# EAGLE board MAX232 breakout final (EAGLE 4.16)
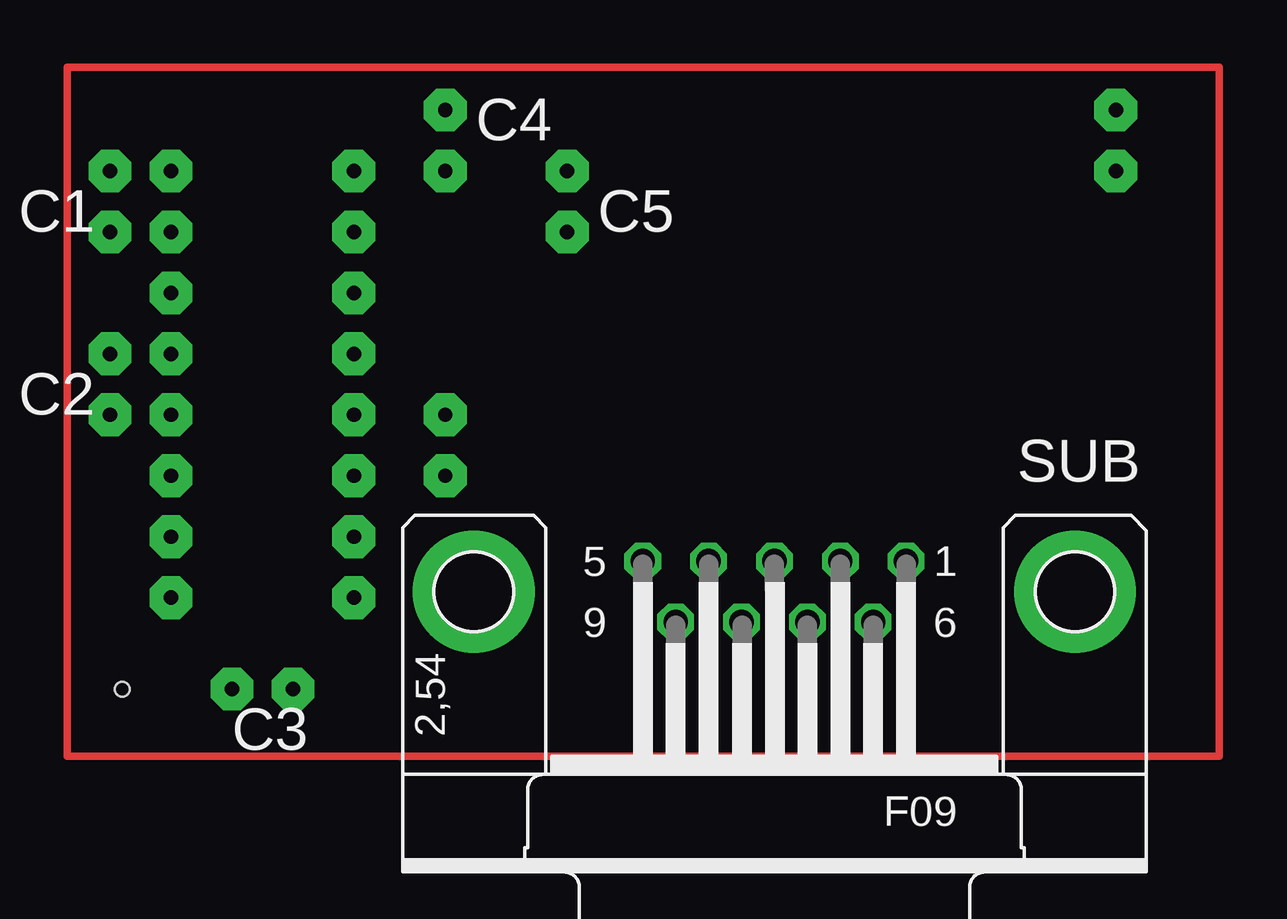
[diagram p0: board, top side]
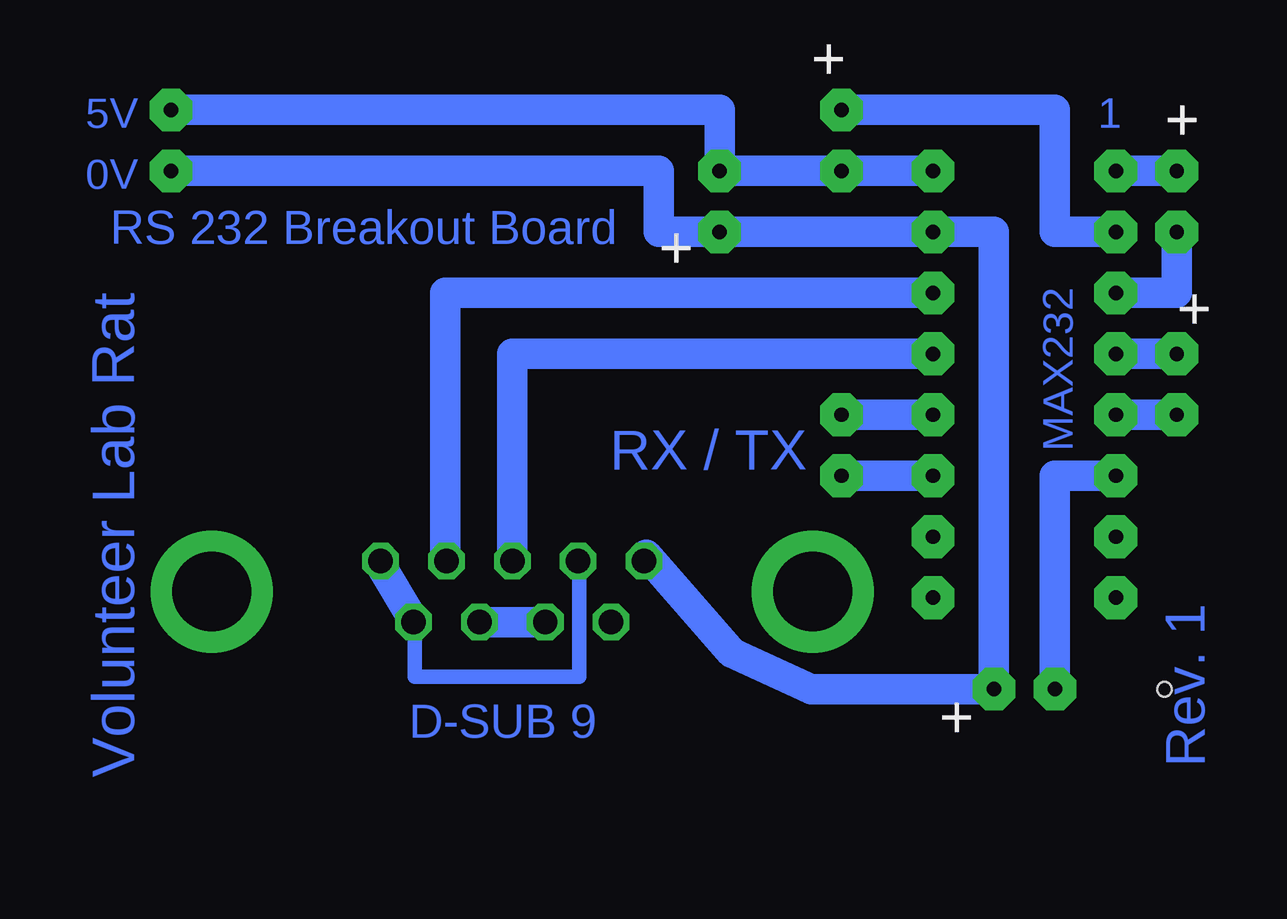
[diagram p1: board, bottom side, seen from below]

No outline drawn. Coordinates in mm, seen from the top.
Copper layers (1*16): Top 0.035mm / dielectric 1.5mm / Bottom 0.035mm
Design rules "default": minimum track width 10mil, minimum drill 24mil, track to track 8mil, track to pad 8mil, pad to pad 8mil, via to via 8mil, smd to smd 8mil, copper to edge 40mil, drill to drill 8mil, minimum pad ring 10mil, minimum via ring 8mil, stop-mask expansion 4mil, vias tented up to drill 0mil, thermal gap 10mil
Holes 0.6 mm at 25.91,22.86

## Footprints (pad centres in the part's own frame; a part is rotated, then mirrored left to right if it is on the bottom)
F09HP = drill 1.016 octagon: 1 -5.486,-1.27; 2 -2.743,-1.27; 3 0,-1.27; 4 2.743,-1.27; 5 5.486,-1.27; 6 -4.115,1.27; 7 -1.372,1.27; 8 1.372,1.27; 9 4.115,1.27 | drill 3.302 pad 5.08 round: G1 -12.522,0; G2 12.522,0

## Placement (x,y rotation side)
SUB  [F09HP]  53.09,26.92 180 top

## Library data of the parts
SUB = con-subd

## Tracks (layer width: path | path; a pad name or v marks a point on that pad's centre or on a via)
S$1  (via drill 0.6 pad 1.78)
  other vias: 27.94,26.67
S$2  (via drill 0.6 pad 1.78)
  other vias: 27.94,29.21
S$4  (via drill 0.6 pad 1.78)
  Bottom 1.27: v25.4,34.29 v27.94,34.29
S$5  (via drill 0.6 pad 1.78)
  Bottom 1.27: v25.4,36.83 v27.94,36.83
S$6  (via drill 0.6 pad 1.78)
  Bottom 1.27: v25.4,44.45 v27.94,44.45
S$7  (via drill 0.6 pad 1.78)
  Bottom 1.27: v35.56,44.45 v39.37,44.45 v44.45,44.45 44.45,46.99 v67.31,46.99
S$8  (via drill 0.6 pad 1.78)
  Bottom 1.27: 35.31,39.37 55.88,39.37 55.88,28.19
  other vias: 35.56,39.37
S$9  (via drill 0.6 pad 1.78)
  other vias: 35.56,26.67
S$10  (via drill 0.6 pad 1.78)
  other vias: 35.56,29.21
S$11  (via drill 0.6 pad 1.78)
  Bottom 1.27: v35.56,31.75 v39.37,31.75
S$12  (via drill 0.6 pad 1.78)
  Bottom 1.27: v35.56,34.29 v39.37,34.29
S$13  (via drill 0.6 pad 1.78)
  Bottom 1.27: v35.56,36.83 53.09,36.83 53.09,28.19
S$14
  Bottom 1.27: 51.82,25.65 54.36,25.65
S$15  (via drill 0.6 pad 1.78)
  Bottom 1.27: v25.4,41.91 25.4,39.37 v27.94,39.37
S$16
  Bottom 0.61: 57.15,25.65 57.15,23.37 50.29,23.37 50.29,28.45
  Bottom 1.27: 57.15,25.65 58.67,28.19
S$17
  Top 0.305: 23.62,20.07 71.63,20.07 71.63,48.77 23.62,48.77 23.62,20.07
S$19  (via drill 0.6 pad 1.78)
  Bottom 1.27: v27.94,31.75 30.48,31.75 v30.48,22.86
S$20  (via drill 0.6 pad 1.78)
  Bottom 1.27: v27.94,41.91 30.48,41.91 30.48,46.99 v39.37,46.99
S$21  (via drill 0.6 pad 1.78)
  Bottom 1.27: 47.5,28.45 43.94,24.38 40.64,22.86 v33.02,22.86 33.02,41.91 v35.56,41.91 v44.45,41.91 46.99,41.91 46.99,44.45 v67.31,44.45

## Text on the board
Bottom: 1 | 5V | 0V | RS 232 Breakout Board | MAX232 | Volunteer Lab Rat | RX / TX | Rev. 1 | D-SUB 9
tNames: C4 | C1 | C5 | C2 | C3
bNames: + | + | + | + | +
